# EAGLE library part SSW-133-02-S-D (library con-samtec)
THROUGH-HOLE .025" SQ POST SOCKET Source: Samtec SSW.pdf
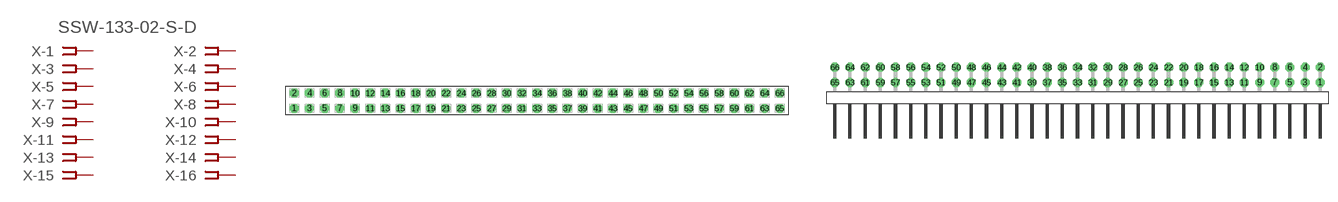
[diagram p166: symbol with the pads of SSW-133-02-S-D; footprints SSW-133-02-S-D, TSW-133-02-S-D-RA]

Designator prefix X; gates -1=FPINV -2=FPIN -3=FPIN -4=FPIN -5=FPIN -6=FPIN -7=FPIN -8=FPIN -9=FPIN -10=FPIN -11=FPIN -12=FPIN -13=FPIN -14=FPIN -15=FPIN -16=FPIN -17=FPIN -18=FPIN -19=FPIN -20=FPIN -21=FPIN -22=FPIN -23=FPIN -24=FPIN -25=FPIN -26=FPIN -27=FPIN -28=FPIN -29=FPIN -30=FPIN -31=FPIN -32=FPIN -33=FPIN -34=FPIN -35=FPIN -36=FPIN -37=FPIN -38=FPIN -39=FPIN -40=FPIN -41=FPIN -42=FPIN -43=FPIN -44=FPIN -45=FPIN -46=FPIN -47=FPIN -48=FPIN -49=FPIN -50=FPIN -51=FPIN -52=FPIN -53=FPIN -54=FPIN -55=FPIN -56=FPIN -57=FPIN -58=FPIN -59=FPIN -60=FPIN -61=FPIN -62=FPIN -63=FPIN -64=FPIN -65=FPIN -66=FPIN

## SSW-133-02-S-D (MPN: SSW-133-02-S-D; OC_FARNELL: unknown; OC_NEWARK: 11P9853)  [SSW-133-02-S-D]
1  -1:1  pas
2  -2:1  pas
3  -3:1  pas
4  -4:1  pas
5  -5:1  pas
6  -6:1  pas
7  -7:1  pas
8  -8:1  pas
9  -9:1  pas
10  -10:1  pas
11  -11:1  pas
12  -12:1  pas
13  -13:1  pas
14  -14:1  pas
15  -15:1  pas
16  -16:1  pas
17  -17:1  pas
18  -18:1  pas
19  -19:1  pas
20  -20:1  pas
21  -21:1  pas
22  -22:1  pas
23  -23:1  pas
24  -24:1  pas
25  -25:1  pas
26  -26:1  pas
27  -27:1  pas
28  -28:1  pas
29  -29:1  pas
30  -30:1  pas
31  -31:1  pas
32  -32:1  pas
33  -33:1  pas
34  -34:1  pas
35  -35:1  pas
36  -36:1  pas
37  -37:1  pas
38  -38:1  pas
39  -39:1  pas
40  -40:1  pas
41  -41:1  pas
42  -42:1  pas
43  -43:1  pas
44  -44:1  pas
45  -45:1  pas
46  -46:1  pas
47  -47:1  pas
48  -48:1  pas
49  -49:1  pas
50  -50:1  pas
51  -51:1  pas
52  -52:1  pas
53  -53:1  pas
54  -54:1  pas
55  -55:1  pas
56  -56:1  pas
57  -57:1  pas
58  -58:1  pas
59  -59:1  pas
60  -60:1  pas
61  -61:1  pas
62  -62:1  pas
63  -63:1  pas
64  -64:1  pas
65  -65:1  pas
66  -66:1  pas

## SSW-133-02-S-D-RA (MPN: SSW-133-02-S-D-RA; OC_FARNELL: unknown; OC_NEWARK: 11P9854)  [TSW-133-02-S-D-RA]
Pads as for SSW-133-02-S-D

## Footprint SSW-133-02-S-D (pad centres in mm)
THROUGH-HOLE .025" SQ POST SOCKET Source: Samtec SSW.pdf
drill 1 pad 1.5 octagon: 1 -40.64,-1.27; 2 -40.64,1.27; 3 -38.1,-1.27; 4 -38.1,1.27; 5 -35.56,-1.27; 6 -35.56,1.27; 7 -33.02,-1.27; 8 -33.02,1.27; 9 -30.48,-1.27; 10 -30.48,1.27; 11 -27.94,-1.27; 12 -27.94,1.27; 13 -25.4,-1.27; 14 -25.4,1.27; 15 -22.86,-1.27; 16 -22.86,1.27; 17 -20.32,-1.27; 18 -20.32,1.27; 19 -17.78,-1.27; 20 -17.78,1.27; 21 -15.24,-1.27; 22 -15.24,1.27; 23 -12.7,-1.27; 24 -12.7,1.27; 25 -10.16,-1.27; 26 -10.16,1.27; 27 -7.62,-1.27; 28 -7.62,1.27; 29 -5.08,-1.27; 30 -5.08,1.27; 31 -2.54,-1.27; 32 -2.54,1.27; 33 0,-1.27; 34 0,1.27; 35 2.54,-1.27; 36 2.54,1.27; 37 5.08,-1.27; 38 5.08,1.27; 39 7.62,-1.27; 40 7.62,1.27; 41 10.16,-1.27; 42 10.16,1.27; 43 12.7,-1.27; 44 12.7,1.27; 45 15.24,-1.27; 46 15.24,1.27; 47 17.78,-1.27; 48 17.78,1.27; 49 20.32,-1.27; 50 20.32,1.27; 51 22.86,-1.27; 52 22.86,1.27; 53 25.4,-1.27; 54 25.4,1.27; 55 27.94,-1.27; 56 27.94,1.27; 57 30.48,-1.27; 58 30.48,1.27; 59 33.02,-1.27; 60 33.02,1.27; 61 35.56,-1.27; 62 35.56,1.27; 63 38.1,-1.27; 64 38.1,1.27; 65 40.64,-1.27; 66 40.64,1.27

## Footprint TSW-133-02-S-D-RA (pad centres in mm)
THROUGH-HOLE .025" SQ POST HEADER Source: Samtec TSW.pdf
drill 1 pad 1.5 octagon: 1 40.64,1.524; 2 40.64,4.064; 3 38.1,1.524; 4 38.1,4.064; 5 35.56,1.524; 6 35.56,4.064; 7 33.02,1.524; 8 33.02,4.064; 9 30.48,1.524; 10 30.48,4.064; 11 27.94,1.524; 12 27.94,4.064; 13 25.4,1.524; 14 25.4,4.064; 15 22.86,1.524; 16 22.86,4.064; 17 20.32,1.524; 18 20.32,4.064; 19 17.78,1.524; 20 17.78,4.064; 21 15.24,1.524; 22 15.24,4.064; 23 12.7,1.524; 24 12.7,4.064; 25 10.16,1.524; 26 10.16,4.064; 27 7.62,1.524; 28 7.62,4.064; 29 5.08,1.524; 30 5.08,4.064; 31 2.54,1.524; 32 2.54,4.064; 33 0,1.524; 34 0,4.064; 35 -2.54,1.524; 36 -2.54,4.064; 37 -5.08,1.524; 38 -5.08,4.064; 39 -7.62,1.524; 40 -7.62,4.064; 41 -10.16,1.524; 42 -10.16,4.064; 43 -12.7,1.524; 44 -12.7,4.064; 45 -15.24,1.524; 46 -15.24,4.064; 47 -17.78,1.524; 48 -17.78,4.064; 49 -20.32,1.524; 50 -20.32,4.064; 51 -22.86,1.524; 52 -22.86,4.064; 53 -25.4,1.524; 54 -25.4,4.064; 55 -27.94,1.524; 56 -27.94,4.064; 57 -30.48,1.524; 58 -30.48,4.064; 59 -33.02,1.524; 60 -33.02,4.064; 61 -35.56,1.524; 62 -35.56,4.064; 63 -38.1,1.524; 64 -38.1,4.064; 65 -40.64,1.524; 66 -40.64,4.064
